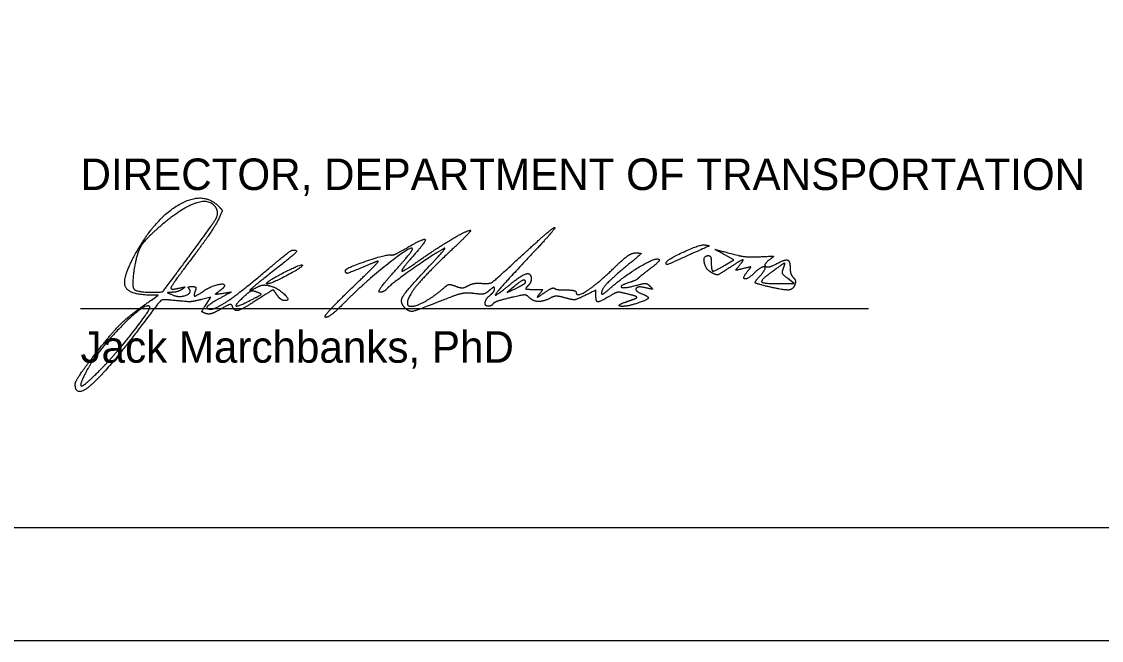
# Model space of a CAD drawing. Extents: x -6.4 to 34, y -1.2 to 22.
# Drawn here: x 25.238 to 30.034, y 0 to 2.748 of the extents above; entities that cross this region are included whole.
import ezdxf

# ---------------------------------------------------------------- set-up
doc = ezdxf.new("R2010")
doc.units = 0
for name, color, linetype in [('GM_X_Airport_Location_Class_3', 7, 'Continuous'), ('GM_X_County', 7, 'Continuous'), ('GM_X_Section', 7, 'Continuous'), ('GM_X_Township', 7, 'Continuous')]:
    doc.layers.add(name, color=color, linetype=linetype)

msp = doc.modelspace()

# ---------------------------------------------------------------- linework, layer by layer
at = {"layer": 'GM_X_Airport_Location_Class_3'}
for p, q in [((25.9623, 1.6782), (25.9623, 1.6782)), ((28.1016, 1.6774), (28.1016, 1.6774)), ((26.3276, 1.5884), (26.3276, 1.5884)), ((27.4766, 1.5904), (27.4766, 1.5904)), ((26.2828, 1.5467), (26.2828, 1.5467)), ((26.6995, 1.5593), (26.6995, 1.5593)), ((28.5541, 1.5712), (28.5541, 1.5712))]:
    msp.add_line(p, q, dxfattribs=at)
for points in [[(28.3654, 1.6678), (28.4018, 1.6893), (28.3611, 1.7123)], [(28.6141, 1.5843), (28.6703, 1.5844), (28.6416, 1.6065)], [(27.4248, 1.5707), (27.3953, 1.5451), (27.436, 1.5648)], [(25.8146, 1.5113), (25.8453, 1.5325), (25.8075, 1.5332)], [(26.0576, 1.4914), (26.0788, 1.5238), (26.0371, 1.5137)]]:
    msp.add_lwpolyline(points, dxfattribs=at)
for points in [[(25.751, 1.729), (25.8372, 1.8794), (26.0454, 1.9954), (26.111, 1.9297)], [(26.1021, 1.9206), (26.0761, 1.9626), (25.95, 1.9214), (25.8547, 1.8398)], [(25.9623, 1.6782), (26.0837, 1.8417), (26.1161, 1.8979), (26.1021, 1.9206)], [(26.111, 1.9297), (26.1298, 1.911), (26.1298, 1.9059), (26.1115, 1.8675)], [(25.8547, 1.8398), (25.788, 1.7828), (25.7492, 1.7186), (25.7381, 1.6474)], [(26.1115, 1.8675), (26.1006, 1.8445), (26.0488, 1.769), (25.9966, 1.6996)], [(27.459, 1.7079), (27.534, 1.777), (27.6, 1.8336), (27.6058, 1.8337)], [(27.6058, 1.8337), (27.6115, 1.8338), (27.5595, 1.7736), (27.4901, 1.7)], [(26.9458, 1.741), (27.0245, 1.7871), (27.0368, 1.7739), (26.9775, 1.7066)], [(27.0047, 1.6875), (27.0853, 1.7441), (27.2166, 1.8213), (27.2323, 1.8213)], [(27.2323, 1.8213), (27.2372, 1.8213), (27.1959, 1.7787), (27.1405, 1.7266)], [(25.8075, 1.5332), (25.7096, 1.5349), (25.6862, 1.616), (25.751, 1.729)], [(26.3411, 1.6555), (26.3916, 1.6984), (26.4371, 1.7335), (26.4422, 1.7336)], [(26.4422, 1.7336), (26.4671, 1.7341), (26.4437, 1.7086), (26.3578, 1.6413)], [(26.9738, 1.7407), (26.9642, 1.7504), (26.7545, 1.5834), (26.6766, 1.5041)], [(27.1141, 1.7403), (27.065, 1.7125), (26.8767, 1.5803), (26.8635, 1.5643)], [(26.8801, 1.7118), (26.8857, 1.7099), (26.9152, 1.7231), (26.9458, 1.741)], [(26.896, 1.6404), (26.9423, 1.6921), (26.9773, 1.7373), (26.9738, 1.7407)], [(27.1405, 1.7266), (27.0409, 1.6329), (26.9516, 1.5247), (26.9516, 1.4978)], [(27.0489, 1.6613), (27.0951, 1.7106), (27.1244, 1.7461), (27.1141, 1.7403)], [(28.1016, 1.6774), (28.1016, 1.6898), (28.2544, 1.7601), (28.2733, 1.7564)], [(28.2733, 1.7564), (28.294, 1.7524), (28.2948, 1.7528), (28.1731, 1.6982)], [(28.3611, 1.7123), (28.3182, 1.7364), (28.3173, 1.7364), (28.4203, 1.71)], [(25.9966, 1.6996), (25.9443, 1.6302), (25.9016, 1.5696), (25.9016, 1.5648)], [(26.6768, 1.6432), (26.677, 1.6537), (26.8644, 1.7169), (26.8801, 1.7118)], [(26.6995, 1.5593), (26.7705, 1.6278), (26.8258, 1.6838), (26.8224, 1.6838)], [(26.8224, 1.6838), (26.819, 1.6838), (26.7899, 1.6726), (26.7578, 1.6588)], [(26.9775, 1.7066), (26.9495, 1.6748), (26.9266, 1.6451), (26.9266, 1.6406)], [(26.9266, 1.6406), (26.9266, 1.6362), (26.9617, 1.6573), (27.0047, 1.6875)], [(27.284, 1.5855), (27.3175, 1.5827), (27.3409, 1.5991), (27.459, 1.7079)], [(27.4901, 1.7), (27.3606, 1.5625), (27.3285, 1.5152), (27.4107, 1.5829)], [(27.8485, 1.5604), (27.9021, 1.6093), (28.049, 1.6993), (28.0659, 1.6936)], [(27.8672, 1.6516), (27.9124, 1.6954), (27.9496, 1.7211), (27.9672, 1.7208)], [(27.9672, 1.7208), (27.9915, 1.7203), (27.9877, 1.7139), (27.9391, 1.6739)], [(28.0659, 1.6936), (28.0743, 1.6908), (28.0591, 1.6721), (28.032, 1.6519)], [(28.1731, 1.6982), (28.1106, 1.67), (28.1016, 1.6674), (28.1016, 1.6774)], [(28.3026, 1.6333), (28.2761, 1.6475), (28.2651, 1.7088), (28.2891, 1.7088)], [(28.2891, 1.7088), (28.296, 1.7088), (28.3016, 1.6948), (28.3016, 1.6776)], [(28.425, 1.663), (28.4494, 1.6926), (28.4336, 1.6888), (28.3773, 1.6516)], [(28.4203, 1.71), (28.441, 1.7047), (28.486, 1.702), (28.5203, 1.7039)], [(28.5203, 1.7039), (28.5752, 1.707), (28.5801, 1.7054), (28.5602, 1.6906)], [(28.5602, 1.6906), (28.5314, 1.6691), (28.5543, 1.6527), (28.588, 1.6707)], [(28.588, 1.6707), (28.6282, 1.6923), (28.6516, 1.6865), (28.6516, 1.6551)], [(25.7381, 1.6474), (25.7267, 1.574), (25.7481, 1.5463), (25.8162, 1.5463)], [(25.8162, 1.5463), (25.8628, 1.5463), (25.8674, 1.5504), (25.9623, 1.6782)], [(26.0797, 1.4713), (26.1028, 1.4713), (26.2289, 1.5601), (26.3411, 1.6555)], [(26.3578, 1.6413), (26.2646, 1.5683), (26.2432, 1.5467), (26.2871, 1.5702)], [(26.3276, 1.5884), (26.348, 1.6062), (26.4801, 1.672), (26.4852, 1.6669)], [(26.4852, 1.6669), (26.4914, 1.6607), (26.3488, 1.5838), (26.3311, 1.5838)], [(26.7578, 1.6588), (26.6952, 1.632), (26.6765, 1.6284), (26.6768, 1.6432)], [(26.8302, 1.5463), (26.8199, 1.5463), (26.8488, 1.5876), (26.896, 1.6404)], [(26.9418, 1.4757), (26.9166, 1.5009), (26.9455, 1.551), (27.0489, 1.6613)], [(27.7016, 1.5448), (27.7016, 1.522), (27.7969, 1.5834), (27.8672, 1.6516)], [(27.9391, 1.6739), (27.8651, 1.6129), (27.8141, 1.5594), (27.8141, 1.5427)], [(28.032, 1.6519), (28.005, 1.6317), (27.98, 1.6117), (27.9766, 1.6075)], [(28.3016, 1.6776), (28.3016, 1.6408), (28.3159, 1.6386), (28.3654, 1.6678)], [(28.3773, 1.6516), (28.3373, 1.6251), (28.324, 1.6218), (28.3026, 1.6333)], [(28.4444, 1.6513), (28.4113, 1.643), (28.4095, 1.6442), (28.425, 1.663)], [(28.4645, 1.6406), (28.4791, 1.6581), (28.4768, 1.6594), (28.4444, 1.6513)], [(28.4932, 1.6318), (28.4613, 1.6018), (28.4382, 1.6089), (28.4645, 1.6406)], [(28.5184, 1.6191), (28.5489, 1.6528), (28.5272, 1.6637), (28.4932, 1.6318)], [(28.6219, 1.652), (28.6317, 1.6778), (28.6235, 1.6747), (28.5609, 1.6291)], [(28.6416, 1.6065), (28.6212, 1.6222), (28.6155, 1.6354), (28.6219, 1.652)], [(28.6516, 1.6551), (28.6516, 1.6393), (28.658, 1.62), (28.6657, 1.6122)], [(26.0457, 1.5507), (26.0746, 1.5705), (26.1391, 1.588), (26.1391, 1.5761)], [(26.3311, 1.5838), (26.3263, 1.5838), (26.3248, 1.5859), (26.3276, 1.5884)], [(27.221, 1.575), (27.2344, 1.5826), (27.2627, 1.5873), (27.284, 1.5855)], [(27.4107, 1.5829), (27.4591, 1.6228), (27.5016, 1.6332), (27.5016, 1.6051)], [(27.4766, 1.5904), (27.4766, 1.6039), (27.4525, 1.5947), (27.4248, 1.5707)], [(27.436, 1.5648), (27.4583, 1.5756), (27.4766, 1.5871), (27.4766, 1.5904)], [(27.5016, 1.6051), (27.5016, 1.5961), (27.4948, 1.5821), (27.4866, 1.5738)], [(27.9422, 1.5909), (27.8927, 1.5755), (27.9122, 1.5618), (27.964, 1.5756)], [(27.9766, 1.6075), (27.9732, 1.6032), (27.9577, 1.5957), (27.9422, 1.5909)], [(27.964, 1.5756), (28.0024, 1.5859), (28.0176, 1.5852), (28.0296, 1.573)], [(28.5541, 1.5712), (28.4994, 1.5841), (28.4936, 1.5918), (28.5184, 1.6191)], [(28.5609, 1.6291), (28.5182, 1.598), (28.5347, 1.5842), (28.6141, 1.5843)], [(28.6657, 1.6122), (28.6735, 1.6044), (28.6765, 1.5892), (28.6724, 1.5784)], [(25.9078, 1.5457), (25.8854, 1.5448), (25.8859, 1.5435), (25.912, 1.533)], [(25.9016, 1.5648), (25.9016, 1.56), (25.9171, 1.5597), (25.936, 1.5641)], [(25.9516, 1.5594), (25.9413, 1.5524), (25.9216, 1.5463), (25.9078, 1.5457)], [(25.912, 1.533), (25.9419, 1.5211), (25.9981, 1.5456), (25.9807, 1.5631)], [(25.936, 1.5641), (25.9615, 1.57), (25.9655, 1.5688), (25.9516, 1.5594)], [(25.9807, 1.5631), (25.9761, 1.5676), (25.9824, 1.5713), (25.9946, 1.5713)], [(25.9946, 1.5713), (26.0092, 1.5713), (26.0143, 1.5649), (26.0096, 1.5526)], [(26.0096, 1.5526), (26.0006, 1.5293), (26.0135, 1.5286), (26.0457, 1.5507)], [(26.1175, 1.552), (26.0986, 1.5382), (26.1005, 1.5369), (26.1331, 1.5418)], [(26.1391, 1.5761), (26.1391, 1.5715), (26.1294, 1.5607), (26.1175, 1.552)], [(26.1331, 1.5418), (26.1699, 1.5474), (26.1697, 1.5471), (26.1243, 1.522)], [(26.2828, 1.5467), (26.2656, 1.5531), (26.2491, 1.5479), (26.2297, 1.5302)], [(26.2547, 1.5104), (26.3011, 1.5341), (26.3047, 1.5387), (26.2828, 1.5467)], [(26.2871, 1.5702), (26.2997, 1.577), (26.3236, 1.5791), (26.3402, 1.5749)], [(26.3732, 1.5335), (26.3564, 1.5576), (26.3543, 1.5571), (26.2886, 1.5147)], [(26.3402, 1.5749), (26.3763, 1.5657), (26.4347, 1.5088), (26.408, 1.5088)], [(26.5891, 1.4345), (26.5788, 1.4347), (26.6284, 1.4909), (26.6995, 1.5593)], [(26.8635, 1.5643), (26.8553, 1.5544), (26.8403, 1.5463), (26.8302, 1.5463)], [(26.9696, 1.4838), (26.9914, 1.4838), (27.0727, 1.529), (27.1091, 1.5613)], [(27.1091, 1.5613), (27.1294, 1.5794), (27.1423, 1.582), (27.166, 1.573)], [(27.247, 1.5404), (27.2178, 1.5441), (27.178, 1.5376), (27.1415, 1.5232)], [(27.166, 1.573), (27.1862, 1.5653), (27.205, 1.566), (27.221, 1.575)], [(27.3165, 1.5548), (27.3008, 1.5406), (27.2796, 1.5362), (27.247, 1.5404)], [(27.3391, 1.5623), (27.3391, 1.5694), (27.3289, 1.566), (27.3165, 1.5548)], [(27.3203, 1.5338), (27.3307, 1.5424), (27.3391, 1.5552), (27.3391, 1.5623)], [(27.4866, 1.5738), (27.4749, 1.5622), (27.4808, 1.5588), (27.5131, 1.5588)], [(27.5131, 1.5588), (27.5507, 1.5588), (27.553, 1.5568), (27.5375, 1.5374)], [(27.5375, 1.5374), (27.5255, 1.5224), (27.532, 1.5242), (27.5592, 1.5433)], [(27.5592, 1.5433), (27.5807, 1.5583), (27.6014, 1.5674), (27.6053, 1.5635)], [(27.6053, 1.5635), (27.6092, 1.5595), (27.6325, 1.5563), (27.657, 1.5563)], [(27.657, 1.5563), (27.6815, 1.5563), (27.7016, 1.5511), (27.7016, 1.5448)], [(27.7891, 1.5323), (27.7891, 1.5552), (27.788, 1.5552), (27.7419, 1.5323)], [(27.8141, 1.5427), (27.8141, 1.5352), (27.8296, 1.5432), (27.8485, 1.5604)], [(27.9342, 1.5372), (27.8954, 1.5471), (27.8786, 1.5455), (27.851, 1.5292)], [(27.9641, 1.518), (27.9755, 1.5222), (27.9638, 1.5297), (27.9342, 1.5372)], [(28.011, 1.5655), (27.9742, 1.5746), (27.961, 1.5515), (27.9953, 1.5383)], [(27.9953, 1.5383), (28.0259, 1.5266), (28.017, 1.5117), (27.9702, 1.4963)], [(28.0296, 1.573), (28.0423, 1.5601), (28.0388, 1.5587), (28.011, 1.5655)], [(28.6724, 1.5784), (28.6643, 1.5573), (28.6231, 1.5548), (28.5541, 1.5712)], [(25.5637, 1.2691), (25.6414, 1.3696), (25.7214, 1.4469), (25.8146, 1.5113)], [(25.8959, 1.5114), (25.8625, 1.5147), (25.8507, 1.5042), (25.7741, 1.4026)], [(26.0371, 1.5137), (25.9967, 1.504), (25.9744, 1.5036), (25.8959, 1.5114)], [(26.0564, 1.4514), (26.0382, 1.4584), (26.0383, 1.462), (26.0576, 1.4914)], [(26.1243, 1.522), (26.0732, 1.4938), (26.0535, 1.4713), (26.0797, 1.4713)], [(26.1741, 1.485), (26.1713, 1.4936), (26.152, 1.4884), (26.123, 1.4712)], [(26.2886, 1.5147), (26.2197, 1.4704), (26.1822, 1.4606), (26.1741, 1.485)], [(26.2297, 1.5302), (26.1855, 1.4897), (26.1967, 1.4808), (26.2547, 1.5104)], [(26.408, 1.5088), (26.3984, 1.5088), (26.3827, 1.5199), (26.3732, 1.5335)], [(26.6766, 1.5041), (26.6388, 1.4657), (26.5994, 1.4343), (26.5891, 1.4345)], [(27.1415, 1.5232), (26.9954, 1.4655), (26.9604, 1.4572), (26.9418, 1.4757)], [(26.9516, 1.4978), (26.9516, 1.4901), (26.9597, 1.4838), (26.9696, 1.4838)], [(27.3134, 1.4838), (27.295, 1.4838), (27.2995, 1.5166), (27.3203, 1.5338)], [(27.3315, 1.4942), (27.328, 1.4885), (27.3198, 1.4838), (27.3134, 1.4838)], [(27.4077, 1.5213), (27.3693, 1.5121), (27.335, 1.4999), (27.3315, 1.4942)], [(27.492, 1.5234), (27.4809, 1.5345), (27.4608, 1.534), (27.4077, 1.5213)], [(27.5883, 1.5209), (27.5576, 1.5044), (27.5097, 1.5057), (27.492, 1.5234)], [(27.6528, 1.521), (27.6259, 1.5287), (27.6028, 1.5287), (27.5883, 1.5209)], [(27.7419, 1.5323), (27.7045, 1.5138), (27.6859, 1.5115), (27.6528, 1.521)], [(27.851, 1.5292), (27.806, 1.5026), (27.7891, 1.5035), (27.7891, 1.5323)], [(27.9702, 1.4963), (27.9236, 1.4809), (27.8763, 1.4866), (27.9203, 1.5023)], [(27.9203, 1.5023), (27.9341, 1.5072), (27.9538, 1.5143), (27.9641, 1.518)], [(25.8075, 1.4821), (25.7866, 1.503), (25.5681, 1.2773), (25.5218, 1.1869)], [(25.5919, 1.2057), (25.6595, 1.2748), (25.8152, 1.4744), (25.8075, 1.4821)], [(26.123, 1.4712), (26.0973, 1.4561), (26.0674, 1.4472), (26.0564, 1.4514)], [(25.7741, 1.4026), (25.6217, 1.2005), (25.4766, 1.0718), (25.4766, 1.1388)], [(25.4766, 1.1388), (25.4766, 1.1485), (25.5158, 1.2071), (25.5637, 1.2691)], [(25.5218, 1.1869), (25.4905, 1.126), (25.5222, 1.1345), (25.5919, 1.2057)]]:
    msp.add_open_spline(points, degree=2, dxfattribs=at)
at = {"layer": 'GM_X_County'}
msp.add_lwpolyline([(1.5, 21.5), (33.5, 21.5), (33.5, 0.5), (1.5, 0.5)], close=True, dxfattribs=at)
at = {"layer": 'GM_X_Section'}
msp.add_lwpolyline([(0, 0), (34, 0), (34, 22), (0, 22)], close=True, dxfattribs=at)
at = {"layer": 'GM_X_Township'}
msp.add_line((25.5, 1.4732), (29, 1.4732), dxfattribs=at)

# ---------------------------------------------------------------- texts
at = {"layer": 'GM_X_Airport_Location_Class_3'}
for s, p in [('DIRECTOR, DEPARTMENT OF TRANSPORTATION', (25.5, 2)), ('Jack Marchbanks, PhD', (25.5, 1.2332))]:
    msp.add_text(s, height=0.14, dxfattribs=at).set_placement(p)

doc.saveas('drawing.dxf')
